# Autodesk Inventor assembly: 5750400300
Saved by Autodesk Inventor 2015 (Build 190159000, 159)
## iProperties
Created: 2020-07
Part Number: 5750400300
Checked By: TraceParts S.A.
Catalog Web Link: www.traceparts.com
Document SubType Name: Assembly
Designer: TraceParts
Company: TraceParts S.A.
Author: TraceParts
REFERENCE: 5750400300
DESIGN: HXBR-400 ECOWATT (230V50/60HZ) V5 - 5750400300
SUPPLIER: Soler & Palau
TraceParts.PartNumber: 10-20122018-119605
TraceParts.PartTitle: HXBR-ECOWATT
TraceParts.InstanceId: 10-20122018-119605CFEJTD86GDEKVOHHDO4UBS566
TraceParts.PartStatus: Published
TraceParts.PartVersion: 1.0.2
TRACEPARTS: TRACEPARTS
TraceParts.PartLanguage: en
TraceParts.ClassPath: SOLER_PALAU:10-20122018-119605
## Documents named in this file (3)
- C:\TPO v2\SharedFS\Outgoing\5750400300.iam
- C:\TPO v2\SharedFS\Outgoing\5750400300_01.ipt
- C:\TPO v2\SharedFS\Outgoing\5750400300_02.ipt
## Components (2 placed, 2 different names)
1. 5750400300_01:1
2. 5750400300_02:1
